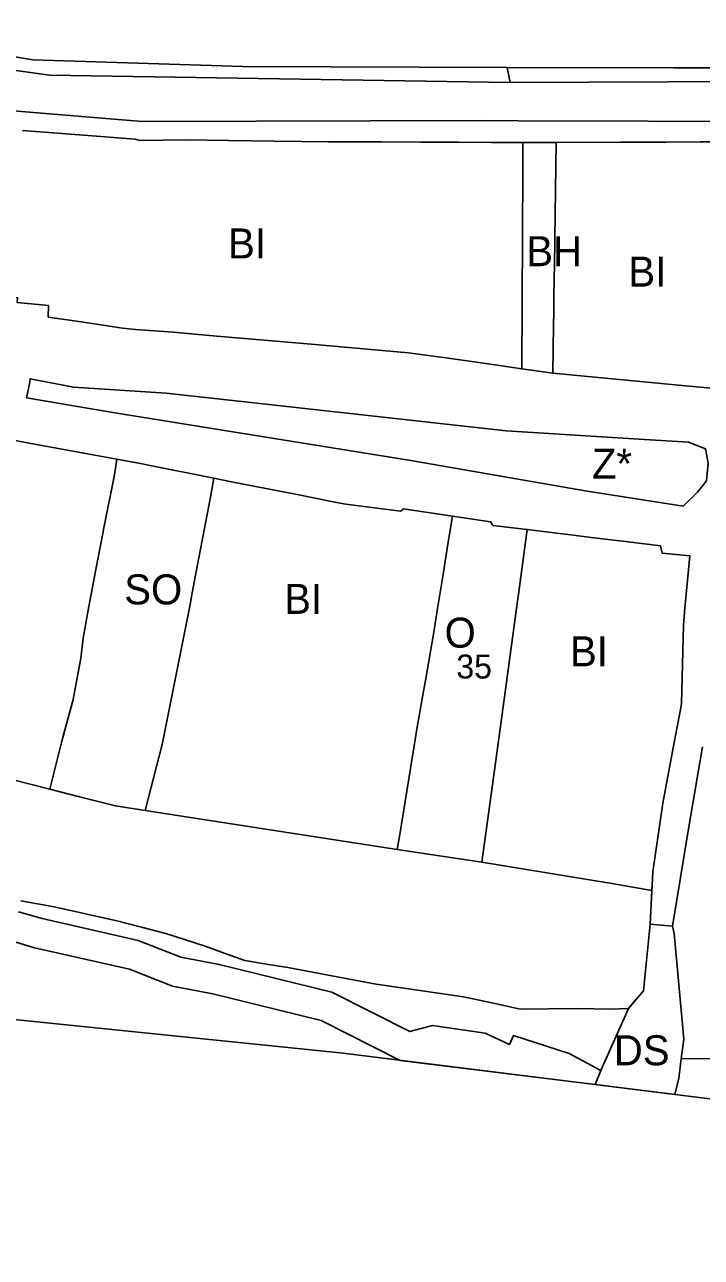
# Model space of a CAD drawing. Extents: x -521621 to -516769, y -1190068 to -1185078.
# Drawn here: x -519527.8 to -519302, y -1187581.5 to -1187170.7 of the extents above; entities that cross this region are included whole.
import ezdxf

# ---------------------------------------------------------------- set-up
doc = ezdxf.new("R2010")
doc.units = 0
for name, color, linetype in [('bydleni_s', 7, 'Continuous'), ('fpl_id', 7, 'Continuous'), ('s_zelen_s', 7, 'Continuous'), ('sm_vyuziti_s', 7, 'Continuous'), ('v_infrastr_n', 7, 'Continuous'), ('v_infrastr_s', 7, 'Continuous'), ('voda_s', 7, 'Continuous')]:
    doc.layers.add(name, color=color, linetype=linetype)

msp = doc.modelspace()

# ---------------------------------------------------------------- linework, layer by layer
at = {"layer": 'bydleni_s'}
for p, q in [((-519437.45, -1187327.25), (-519451.34, -1187324.55)), ((-519423.69, -1187329.93), (-519437.45, -1187327.25))]:
    msp.add_line(p, q, dxfattribs=at)
for points in [[(-519528.42, -1187206.07), (-519518.19, -1187206.84)], [(-519518.19, -1187206.84), (-519506.66, -1187207.73)], [(-519506.66, -1187207.73), (-519490.92, -1187208.94)], [(-519490.92, -1187208.94), (-519489.23, -1187209.37), (-519473.84, -1187209.16)], [(-519473.84, -1187209.16), (-519459.76, -1187209.34)], [(-519459.76, -1187209.34), (-519444.51, -1187209.53)], [(-519444.51, -1187209.53), (-519426.4, -1187209.76)], [(-519426.4, -1187209.76), (-519408.8, -1187209.83)], [(-519408.8, -1187209.83), (-519395.65, -1187209.87)], [(-519395.65, -1187209.87), (-519383.07, -1187209.92)], [(-519383.07, -1187209.92), (-519372, -1187209.96)], [(-519372, -1187209.96), (-519361.54, -1187210)], [(-519351.22, -1187262.12), (-519351.11, -1187254.62), (-519351.07, -1187251.58), (-519350.94, -1187242), (-519350.51, -1187209.97), (-519361.54, -1187210), (-519361.75, -1187250), (-519361.77, -1187254.01), (-519361.82, -1187262.04)], [(-519361.54, -1187210), (-519361.75, -1187250), (-519361.77, -1187254.01), (-519361.82, -1187262.04)], [(-519351.22, -1187262.12), (-519351.11, -1187254.62), (-519351.07, -1187251.58), (-519350.94, -1187242), (-519350.51, -1187209.97)], [(-519350.51, -1187209.97), (-519329.02, -1187209.91)], [(-519329.02, -1187209.91), (-519313.86, -1187209.86)], [(-519313.86, -1187209.86), (-519302.43, -1187209.83)], [(-519302.43, -1187209.83), (-519291.24, -1187209.8)], [(-519519.83, -1187264.35), (-519530.22, -1187263.31), (-519530.1, -1187261.78)], [(-519361.82, -1187262.04), (-519361.86, -1187270.68), (-519361.9, -1187277.83), (-519361.94, -1187285.38), (-519351.55, -1187286.84)], [(-519361.82, -1187262.04), (-519361.86, -1187270.68), (-519361.9, -1187277.83), (-519361.94, -1187285.38)], [(-519351.55, -1187286.84), (-519351.33, -1187270.76), (-519351.28, -1187266.58), (-519351.22, -1187262.12)], [(-519351.55, -1187286.84), (-519351.33, -1187270.76), (-519351.28, -1187266.58), (-519351.22, -1187262.12)], [(-519509.72, -1187269.62), (-519519.87, -1187268.2), (-519519.83, -1187264.35)], [(-519495.12, -1187271.89), (-519506.63, -1187270.05), (-519509.72, -1187269.62)], [(-519478.27, -1187273.26), (-519490.83, -1187272.3), (-519495.12, -1187271.89)], [(-519463.63, -1187274.53), (-519478.27, -1187273.26)], [(-519446.52, -1187276.02), (-519463.63, -1187274.53)], [(-519430.8, -1187277.38), (-519446.52, -1187276.02)], [(-519413.54, -1187278.88), (-519430.8, -1187277.38)], [(-519399.71, -1187280.08), (-519413.54, -1187278.88)], [(-519387.31, -1187281.82), (-519399.71, -1187280.08)], [(-519373.89, -1187283.7), (-519387.31, -1187281.82)], [(-519361.94, -1187285.38), (-519373.89, -1187283.7)], [(-519329.39, -1187288.96), (-519351.55, -1187286.84)], [(-519309.64, -1187290.85), (-519329.39, -1187288.96)], [(-519298.75, -1187291.89), (-519309.64, -1187290.85)], [(-519526.24, -1187310.19), (-519531.59, -1187309.22), (-519534.65, -1187308.67)], [(-519508.02, -1187313.51), (-519526.24, -1187310.19)], [(-519508.25, -1187375.19), (-519506.3, -1187364.67), (-519504.01, -1187352.32), (-519501.66, -1187340.3), (-519501.3, -1187338.46), (-519497.84, -1187320.76), (-519497.02, -1187315.51)], [(-519499.5, -1187315.06), (-519508.02, -1187313.51)], [(-519497.02, -1187315.51), (-519499.5, -1187315.06)], [(-519464.6, -1187321.92), (-519465.8, -1187328.22), (-519470.73, -1187354.17), (-519472.2, -1187361.89), (-519472.49, -1187363.39), (-519474.16, -1187371.73), (-519476.05, -1187381.21)], [(-519451.34, -1187324.55), (-519458.75, -1187323.11), (-519464.6, -1187321.92)], [(-519910.14, -1187330.77), (-519908.88, -1187361.03), (-519907.62, -1187386.73), (-519876.89, -1187385.18), (-519794.89, -1187375.93), (-519729.3, -1187378.37), (-519629.4, -1187395.78), (-519562.67, -1187414.49), (-519519.39, -1187425.49)], [(-519408.55, -1187332.04), (-519420.63, -1187330.52), (-519423.69, -1187329.93)], [(-519402.27, -1187332.83), (-519408.55, -1187332.04)], [(-519395.59, -1187397.94), (-519395.24, -1187395.97), (-519394.08, -1187389.28), (-519391.27, -1187373.19), (-519390, -1187365.25), (-519388.2, -1187354.01), (-519387.49, -1187349.53), (-519386.81, -1187345.32), (-519385.08, -1187334.48), (-519401.34, -1187332.06), (-519402.27, -1187332.83)], [(-519343.02, -1187341.09), (-519360.16, -1187339.01), (-519362.97, -1187359.69), (-519363.29, -1187362.04), (-519363.84, -1187366.05), (-519368.47, -1187400.46)], [(-519325.6, -1187343.21), (-519339.66, -1187341.5), (-519343.02, -1187341.09)], [(-519315.08, -1187346.88), (-519315.69, -1187344.41), (-519325.6, -1187343.21)], [(-519311.08, -1187409.95), (-519308.93, -1187398.37), (-519308.67, -1187396.95), (-519308.05, -1187370.8), (-519307.52, -1187365.15), (-519305.89, -1187347.72), (-519315.08, -1187346.88)], [(-519519.39, -1187425.49), (-519515.35, -1187409.49), (-519511.57, -1187395.6), (-519509.02, -1187381.79), (-519508.25, -1187375.19)], [(-519476.05, -1187381.21), (-519481.94, -1187410.65), (-519487.56, -1187432.59), (-519403.45, -1187445.56), (-519402.62, -1187440.63), (-519396.68, -1187404.21), (-519395.59, -1187397.94)], [(-519368.47, -1187400.46), (-519372.15, -1187427.24), (-519375.25, -1187449.81)], [(-519375.25, -1187449.81), (-519331.88, -1187456.93), (-519318.57, -1187459.29), (-519318.24, -1187453.05), (-519314.84, -1187430.21), (-519311.08, -1187409.95)]]:
    msp.add_lwpolyline(points, dxfattribs=at)
at = {"layer": 's_zelen_s'}
for points in [[(-519976.25, -1186969.59), (-519973.89, -1186964.34), (-519945.18, -1186982.09), (-519941.17, -1186985.33), (-519876.04, -1187044.95), (-519872.07, -1187048.29), (-519870.88, -1187049.41), (-519831.64, -1187086.03), (-519782.87, -1187121.37), (-519783.03, -1187122.14), (-519711.27, -1187163.96), (-519691.98, -1187171.68), (-519636.11, -1187188.04), (-519566.51, -1187196.52), (-519488.58, -1187203.01), (-519374.38, -1187202.7), (-519363.08, -1187202.74), (-519276.38, -1187203.01), (-519187.84, -1187203.66), (-519142.54, -1187204.74), (-519110.53, -1187206.31), (-519088.84, -1187207.37)], [(-519122.7, -1187191.89), (-519260.22, -1187189.55), (-519365.76, -1187190.07), (-519366.84, -1187184.99), (-519311.33, -1187185.14), (-519272.36, -1187185.14), (-519160.43, -1187185.04), (-519119.53, -1187185.92)], [(-519291.24, -1187209.8), (-519302.43, -1187209.83), (-519313.86, -1187209.86), (-519329.02, -1187209.91), (-519350.51, -1187209.97), (-519361.54, -1187210), (-519372, -1187209.96), (-519383.07, -1187209.92), (-519395.65, -1187209.87), (-519408.8, -1187209.83), (-519426.4, -1187209.76), (-519444.51, -1187209.53), (-519459.76, -1187209.34), (-519473.84, -1187209.16), (-519489.23, -1187209.37), (-519490.92, -1187208.94), (-519506.66, -1187207.73), (-519518.19, -1187206.84), (-519528.42, -1187206.07)], [(-519340.83, -1187326.07), (-519308.14, -1187331.14), (-519303.3, -1187326.48), (-519300.34, -1187322.71), (-519299.8, -1187316.88), (-519300.01, -1187315.67), (-519300.61, -1187312.13), (-519306.33, -1187309.9), (-519322.8, -1187308.87), (-519367.14, -1187306.08), (-519395.14, -1187302.99), (-519449.32, -1187297), (-519480.57, -1187293.55), (-519511.5, -1187291.57), (-519525.87, -1187288.75), (-519526.08, -1187289.83), (-519527.1, -1187295.05), (-519498.34, -1187299.98), (-519398.99, -1187315.96), (-519340.83, -1187326.07)], [(-519519.39, -1187425.49), (-519562.67, -1187414.49), (-519629.4, -1187395.78), (-519729.3, -1187378.37), (-519794.89, -1187375.93), (-519876.89, -1187385.18), (-519907.62, -1187386.73)], [(-519509.51, -1187428), (-519519.39, -1187425.49)], [(-519487.56, -1187432.59), (-519497.48, -1187431.06), (-519509.51, -1187428)], [(-519403.45, -1187445.56), (-519487.56, -1187432.59)], [(-519375.25, -1187449.81), (-519403.45, -1187445.56)], [(-519318.57, -1187459.29), (-519331.88, -1187456.93), (-519375.25, -1187449.81)], [(-519529.01, -1187462.73), (-519523.46, -1187463.74), (-519517.9, -1187464.74), (-519507.45, -1187467.05), (-519496.99, -1187469.37), (-519488.81, -1187471.49), (-519480.63, -1187473.61), (-519474.07, -1187475.74), (-519467.51, -1187477.86), (-519460.92, -1187480.22), (-519454.32, -1187482.57), (-519447.14, -1187483.77), (-519439.96, -1187484.96), (-519425.26, -1187487.74), (-519410.56, -1187490.51), (-519395.98, -1187492.59), (-519381.4, -1187494.68), (-519371.91, -1187496.73), (-519362.42, -1187498.77), (-519353.04, -1187498.69), (-519343.67, -1187498.61), (-519337.96, -1187498.69), (-519332.25, -1187498.77), (-519329.32, -1187498.66), (-519326.38, -1187498.54), (-519323.86, -1187495.62), (-519321.33, -1187492.71), (-519320.25, -1187481.6), (-519319.17, -1187470.49), (-519318.57, -1187459.29)]]:
    msp.add_lwpolyline(points, dxfattribs=at)
at = {"layer": 'sm_vyuziti_s'}
for points in [[(-519497.02, -1187315.51), (-519497.84, -1187320.76), (-519501.3, -1187338.46), (-519501.66, -1187340.3), (-519504.01, -1187352.32), (-519506.3, -1187364.67), (-519508.25, -1187375.19)], [(-519476.05, -1187381.21), (-519474.16, -1187371.73), (-519472.49, -1187363.39), (-519472.2, -1187361.89), (-519470.73, -1187354.17), (-519465.8, -1187328.22), (-519464.6, -1187321.92), (-519485.9, -1187317.6), (-519489.15, -1187316.94), (-519497.02, -1187315.51)], [(-519508.25, -1187375.19), (-519509.02, -1187381.79), (-519511.57, -1187395.6), (-519515.35, -1187409.49), (-519519.39, -1187425.49), (-519509.51, -1187428)], [(-519481.94, -1187410.65), (-519476.05, -1187381.21)], [(-519487.56, -1187432.59), (-519481.94, -1187410.65)], [(-519509.51, -1187428), (-519497.48, -1187431.06), (-519487.56, -1187432.59)]]:
    msp.add_lwpolyline(points, dxfattribs=at)
at = {"layer": 'v_infrastr_n'}
for points in [[(-519395.24, -1187395.97), (-519394.08, -1187389.28), (-519391.27, -1187373.19), (-519390, -1187365.25), (-519388.2, -1187354.01), (-519387.49, -1187349.53), (-519386.81, -1187345.32), (-519385.08, -1187334.48), (-519372.33, -1187336.38), (-519371.56, -1187337.62), (-519360.16, -1187339.01), (-519362.97, -1187359.69), (-519363.29, -1187362.04), (-519363.84, -1187366.05), (-519368.47, -1187400.46)], [(-519375.25, -1187449.81), (-519403.45, -1187445.56), (-519402.62, -1187440.63), (-519396.68, -1187404.21), (-519395.59, -1187397.94), (-519395.24, -1187395.97)], [(-519368.47, -1187400.46), (-519372.15, -1187427.24), (-519375.25, -1187449.81)], [(-519262.71, -1187515.06), (-519308.73, -1187515.41), (-519307.91, -1187508.76), (-519311.13, -1187473.61), (-519311.66, -1187471.13), (-519306.32, -1187438.74), (-519301.65, -1187411.41)], [(-519529.82, -1187466.32), (-519521.95, -1187468.64), (-519489.85, -1187475.89), (-519475.65, -1187481.45), (-519462.84, -1187483.92), (-519425.34, -1187493.18), (-519399.26, -1187506.29), (-519391.7, -1187504.29), (-519374.11, -1187506.76), (-519366.08, -1187510.61), (-519364.69, -1187507.53), (-519346.17, -1187513.55), (-519335.52, -1187519.26), (-519337.51, -1187523.93), (-519402.49, -1187515.86), (-519428.83, -1187502.62), (-519464.99, -1187493.69), (-519478.44, -1187491.1), (-519492.79, -1187485.48), (-519524.47, -1187478.32), (-519532.13, -1187476.06)], [(-519790.94, -1187475.66), (-519421.47, -1187513.5), (-519006.29, -1187565.08), (-518941.03, -1187571.03), (-518921.54, -1187583.59)]]:
    msp.add_lwpolyline(points, dxfattribs=at)
at = {"layer": 'v_infrastr_s'}
for p, q in [((-519495.12, -1187271.89), (-519506.63, -1187270.05)), ((-519490.83, -1187272.3), (-519495.12, -1187271.89)), ((-519478.27, -1187273.26), (-519490.83, -1187272.3)), ((-519321.33, -1187492.71), (-519319.17, -1187470.49)), ((-519319.17, -1187470.49), (-519315.42, -1187470.81)), ((-519315.42, -1187470.81), (-519311.66, -1187471.13)), ((-519311.66, -1187471.13), (-519311.13, -1187473.61)), ((-519326.38, -1187498.54), (-519321.33, -1187492.71)), ((-519307.91, -1187508.76), (-519308.73, -1187515.41)), ((-519308.73, -1187515.41), (-519309.52, -1187521.84)), ((-519337.51, -1187523.93), (-519335.52, -1187519.26)), ((-519309.52, -1187521.84), (-519310.89, -1187527.24))]:
    msp.add_line(p, q, dxfattribs=at)
for points in [[(-519525.02, -1187182.45), (-519576.25, -1187173.88)], [(-519454.95, -1187184.74), (-519525.02, -1187182.45)], [(-519366.84, -1187184.99), (-519454.95, -1187184.74)], [(-519311.33, -1187185.14), (-519366.84, -1187184.99)], [(-519272.36, -1187185.14), (-519311.33, -1187185.14)], [(-519506.63, -1187270.05), (-519509.72, -1187269.62), (-519519.87, -1187268.2), (-519519.83, -1187264.35), (-519530.22, -1187263.31), (-519530.1, -1187261.78), (-519540.33, -1187260.82), (-519540.49, -1187262.59), (-519545.51, -1187262.1), (-519545.47, -1187259.34), (-519550.52, -1187259.06), (-519550.28, -1187255.93), (-519567.27, -1187254.65), (-519570.68, -1187254.39), (-519584.02, -1187250.22), (-519596.96, -1187246.17), (-519609.99, -1187242.09), (-519623.65, -1187237.81), (-519634.88, -1187234.3), (-519636.03, -1187233.94)], [(-519298.75, -1187291.89), (-519309.64, -1187290.85), (-519329.39, -1187288.96), (-519351.55, -1187286.84), (-519361.94, -1187285.38), (-519373.89, -1187283.7), (-519387.31, -1187281.82), (-519399.71, -1187280.08), (-519413.54, -1187278.88), (-519430.8, -1187277.38), (-519446.52, -1187276.02), (-519463.63, -1187274.53), (-519478.27, -1187273.26)], [(-519340.83, -1187326.07), (-519398.99, -1187315.96), (-519498.34, -1187299.98), (-519527.1, -1187295.05), (-519526.08, -1187289.83), (-519525.87, -1187288.75), (-519511.5, -1187291.57), (-519480.57, -1187293.55), (-519449.32, -1187297), (-519395.14, -1187302.99), (-519367.14, -1187306.08), (-519322.8, -1187308.87), (-519306.33, -1187309.9), (-519300.61, -1187312.13), (-519300.01, -1187315.67), (-519299.8, -1187316.88), (-519300.34, -1187322.71), (-519303.3, -1187326.48), (-519308.14, -1187331.14), (-519340.83, -1187326.07)], [(-519531.59, -1187309.22), (-519526.24, -1187310.19), (-519508.02, -1187313.51), (-519499.5, -1187315.06), (-519489.15, -1187316.94), (-519485.9, -1187317.6), (-519464.6, -1187321.92), (-519458.75, -1187323.11), (-519451.34, -1187324.55), (-519437.45, -1187327.25), (-519423.69, -1187329.93), (-519420.63, -1187330.52), (-519408.55, -1187332.04), (-519402.27, -1187332.83), (-519401.34, -1187332.06), (-519385.08, -1187334.48), (-519372.33, -1187336.38), (-519371.56, -1187337.62), (-519360.16, -1187339.01), (-519343.02, -1187341.09), (-519339.66, -1187341.5), (-519325.6, -1187343.21), (-519315.69, -1187344.41), (-519315.08, -1187346.88), (-519305.89, -1187347.72), (-519307.52, -1187365.15), (-519308.05, -1187370.8), (-519308.67, -1187396.95), (-519308.93, -1187398.37), (-519311.08, -1187409.95)], [(-519311.08, -1187409.95), (-519314.84, -1187430.21), (-519318.24, -1187453.05), (-519319.17, -1187470.49)], [(-519311.66, -1187471.13), (-519306.32, -1187438.74), (-519301.65, -1187411.41)], [(-519319.17, -1187470.49), (-519315.42, -1187470.81)], [(-519315.42, -1187470.81), (-519311.66, -1187471.13)], [(-519311.13, -1187473.61), (-519307.91, -1187508.76)], [(-519335.52, -1187519.26), (-519326.38, -1187498.54)], [(-519310.89, -1187527.24), (-519337.51, -1187523.93)]]:
    msp.add_lwpolyline(points, dxfattribs=at)
at = {"layer": 'voda_s'}
for points in [[(-519582.24, -1187178.82), (-519519.49, -1187187.61), (-519366.03, -1187190.07), (-519365.76, -1187190.07), (-519260.22, -1187189.55), (-519122.7, -1187191.89), (-519109.21, -1187192.12), (-519084.08, -1187192.31), (-519020.8, -1187190.92), (-518980.23, -1187191.22), (-518927.11, -1187192.31), (-518908.24, -1187190.95)], [(-518954.5, -1187214.16), (-518975.71, -1187213.9), (-518979.65, -1187213.85), (-518997.62, -1187213.78), (-519000.33, -1187213.77), (-519000.33, -1187208.37), (-519054.11, -1187206.59), (-519063.53, -1187206.13), (-519088.84, -1187207.37), (-519110.53, -1187206.31), (-519142.54, -1187204.74), (-519187.84, -1187203.66), (-519276.38, -1187203.01), (-519363.08, -1187202.74), (-519374.38, -1187202.7), (-519488.58, -1187203.01), (-519566.51, -1187196.52)]]:
    msp.add_lwpolyline(points, dxfattribs=at)

# ---------------------------------------------------------------- texts
at = {"layer": 'bydleni_s'}
for s, p in [('BI', (-519459.89, -1187248.66)), ('BH', (-519360.42, -1187251.23)), ('BI', (-519326.38, -1187258.04)), ('BI', (-519441.18, -1187367.09)), ('BI', (-519345.84, -1187384.56))]:
    msp.add_text(s, height=10, dxfattribs=at).set_placement(p)
at = {"layer": 'fpl_id'}
msp.add_text('35', height=8, dxfattribs=at).set_placement((-519383.79, -1187388.63))
at = {"layer": 's_zelen_s'}
msp.add_text('Z*', height=10, dxfattribs=at).set_placement((-519338.53, -1187322.02))
at = {"layer": 'sm_vyuziti_s'}
msp.add_text('SO', height=10, dxfattribs=at).set_placement((-519494.52, -1187363.92))
at = {"layer": 'v_infrastr_n'}
msp.add_text('O', height=10, dxfattribs=at).set_placement((-519387.68, -1187378.35))
at = {"layer": 'v_infrastr_s'}
msp.add_text('DS', height=10, dxfattribs=at).set_placement((-519331.24, -1187517.5))

doc.saveas('drawing.dxf')
